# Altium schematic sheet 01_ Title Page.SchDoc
size 420 x 297 mm; SheetNumber: 1; SheetTotal: 4
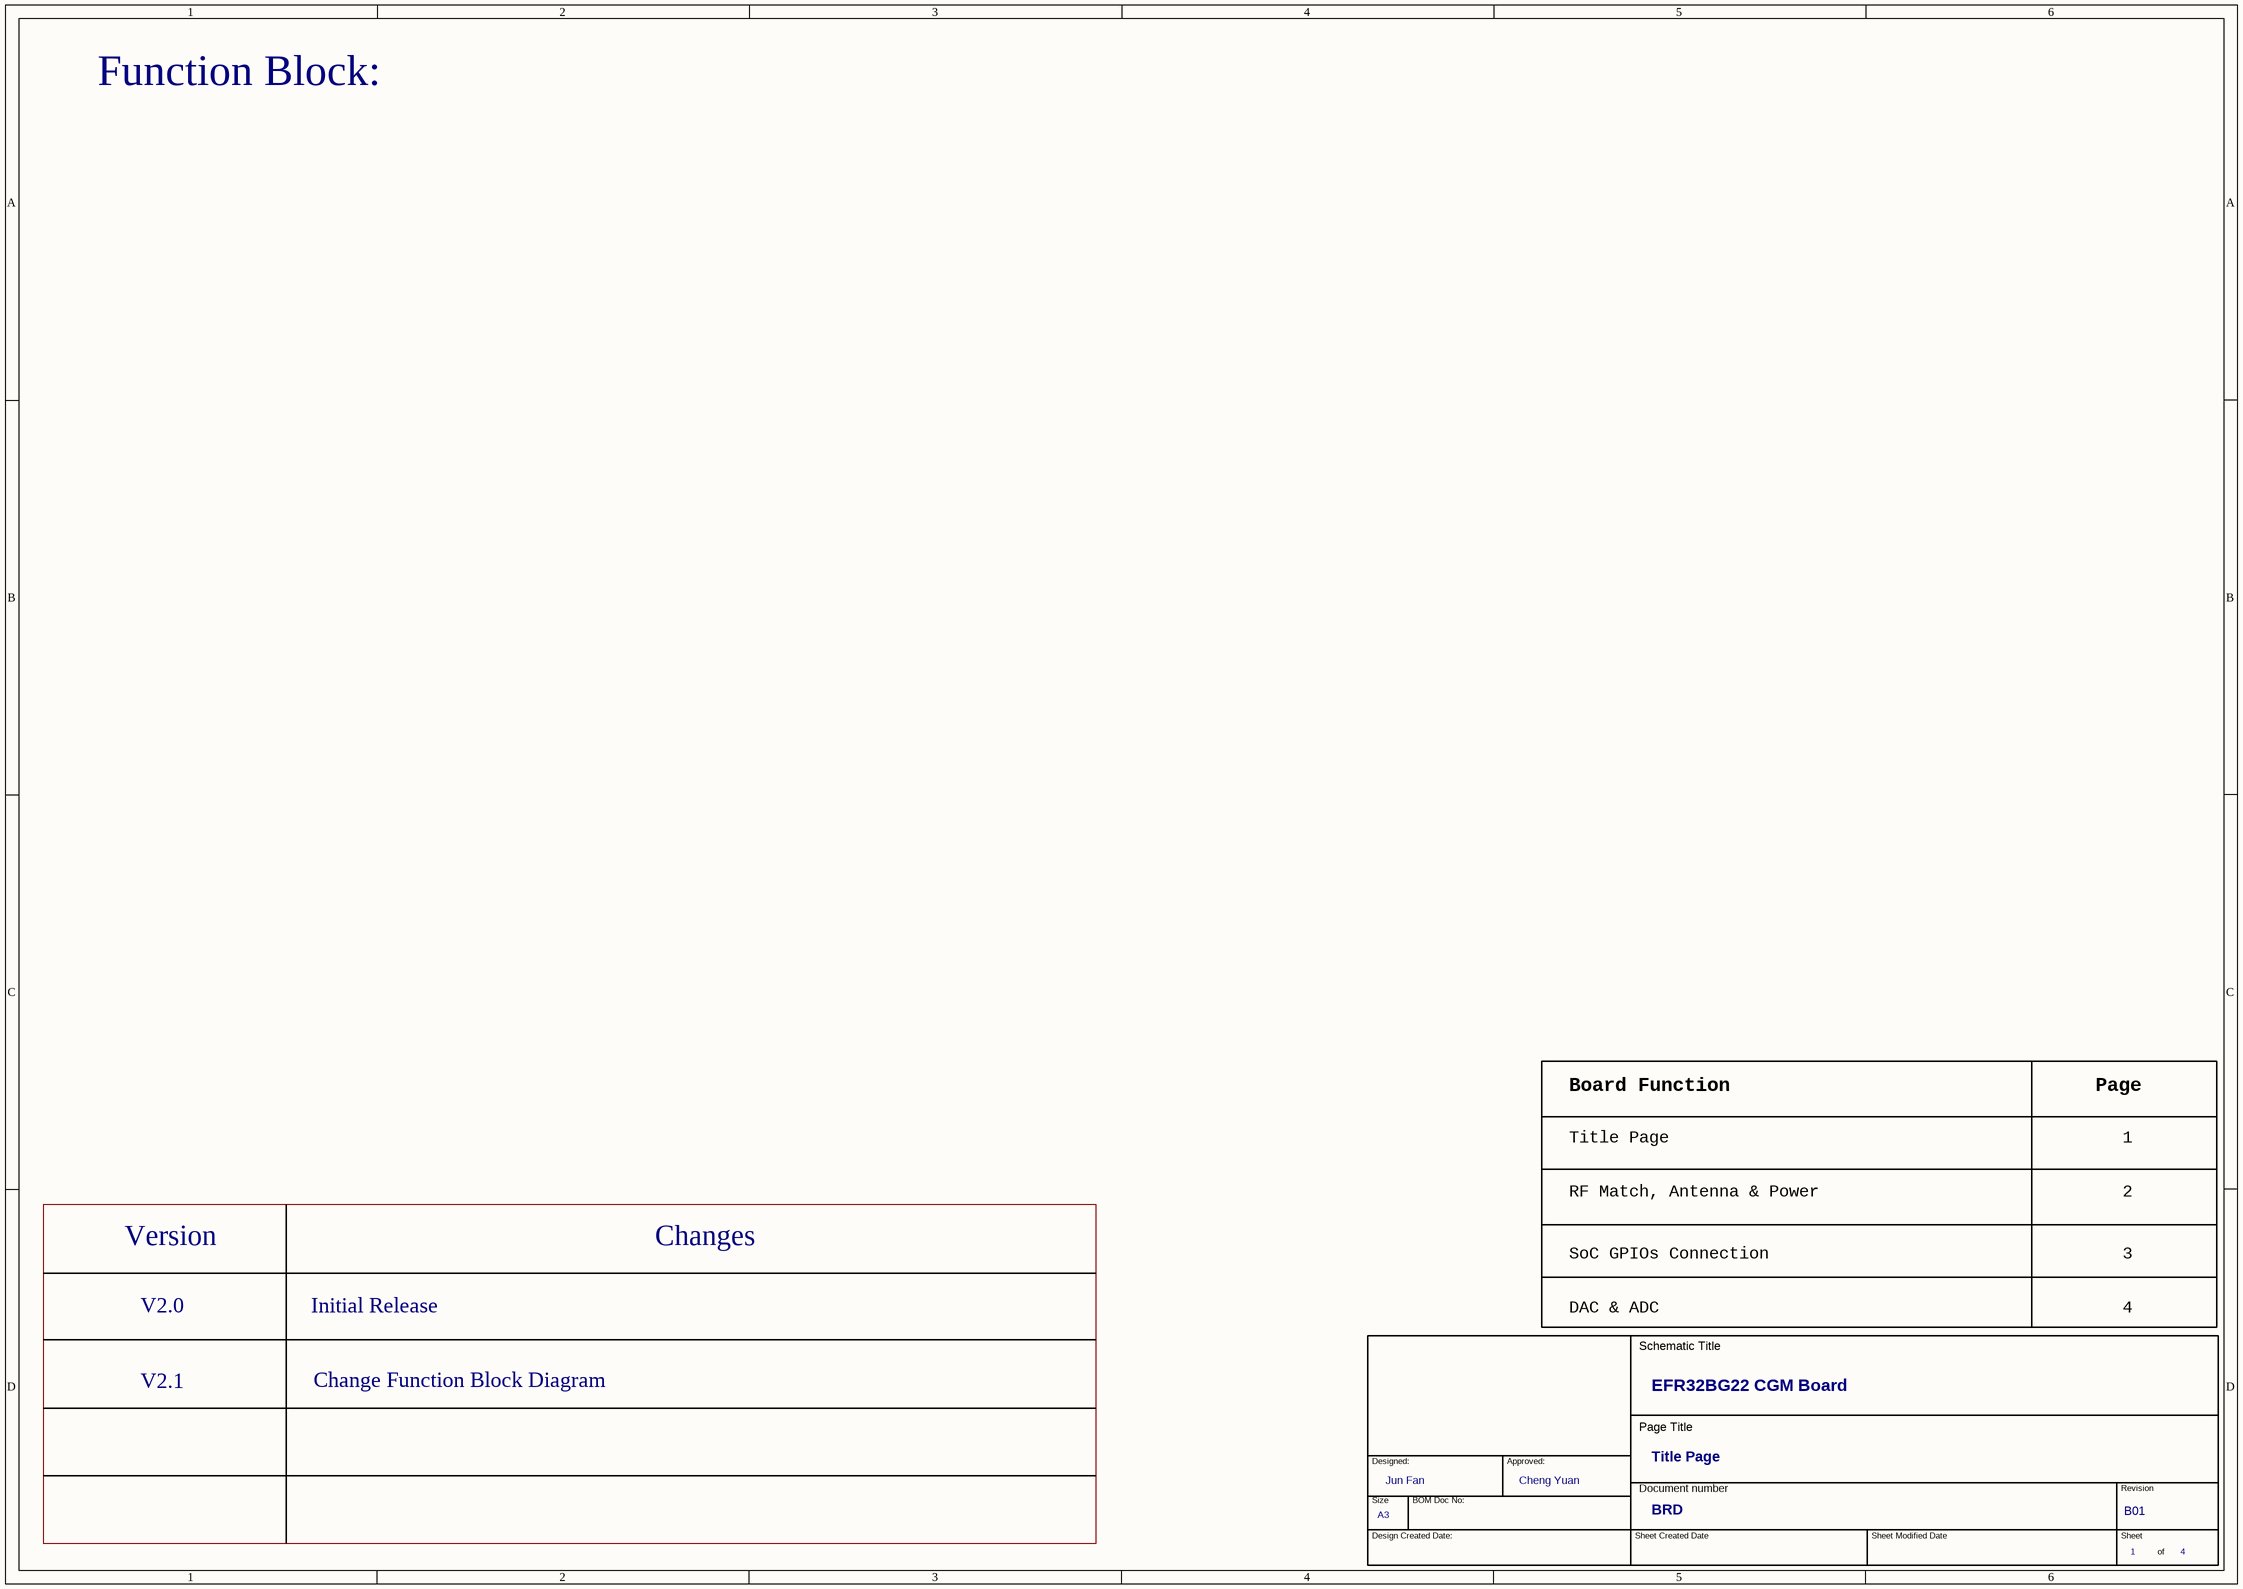
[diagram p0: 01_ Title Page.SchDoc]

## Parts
*?  OrgAddr2: Cheng Yuan  OrgAddr1: Jun Fan  Page Count: 4  Page Number: 1  Doc: BRD  Title: EFR32BG22 CGM Board  RevCode: B01  Page Size: A3  Page Title: Title Page  (hidden comment: TitleBlock_SiLabs_A3)  (graphical)

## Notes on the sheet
- Function Block:
- Board Function
- Page
- RF Match, Antenna & Power
- Title Page
- 1
- 2
- Version
- Changes
- SoC GPIOs Connection
- 3
- V2.0
- Initial Release
- DAC & ADC
- 4
- V2.1
- Change Function Block Diagram

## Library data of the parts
*? = TitleBlock_SiLabs_A3: Cage Code: <Cage Code>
